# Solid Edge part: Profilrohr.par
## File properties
Username: bmolnar
Dokumentum tartalom típus: 0
Author: bmolnar
Last saved by: bmolnar
Revision: 78
Sűrűség: 0,000 kg/m^3
Pontosság: 0,990
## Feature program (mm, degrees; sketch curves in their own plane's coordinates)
base feature "unnamed BaseFeature 1"
thread "unnamed Thread 1"
thread "Menet_2"  ThreadDepth = 7.5 mm
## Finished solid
Body 1: solid body, 139 faces, 282 edges, 180 vertices, 3 separate solids.
  Faces by surface: plane 82, cylinder 33, cone 20, torus 4
  Edges by curve: line 188, circle 86, curve on surface 7, intersection 1
Bounding box of the edges (mm; curved faces can reach further): 65.000 x 70.000 x 54.500, from (-32.5, -32.5, 0) to (32.5, 37.5, 54.5).
Cylindrical faces by radius (mm): R1.375 x2, R3 x2, R3.4 x4, R4.283 x4, R5.45 x2, R5.5 x8, R25 x1, R25.9 x2, R26.1 x2, R27.6 x2, R43 x4
Conical faces (half-angle, radius in mm at the cone's reference point): 30 deg R3.2887 x2, 30 deg R25.325 x2, 30 deg R26.1887 x2, 45 deg R3.25 x2, 45 deg R3.65 x2, 45 deg R4.533 x2, 45 deg R5.2 x4, 45 deg R26.25 x2, 45 deg R26.35 x2
Toroidal faces (ring radius, tube radius in mm): R27.4 r0.2 x4
Planar faces by outward normal: +x 9, +y 11, +z 10, -x 9, -y 9, -z 10, oblique 24
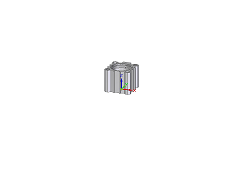
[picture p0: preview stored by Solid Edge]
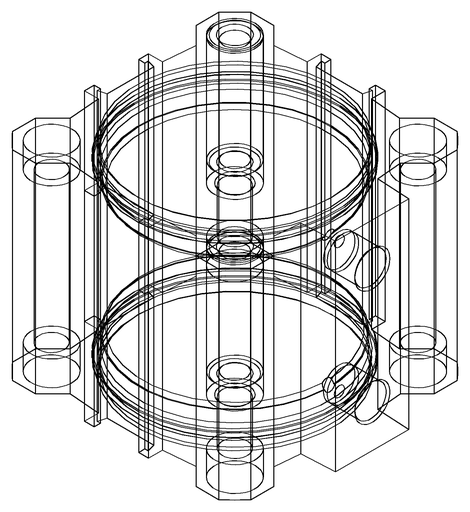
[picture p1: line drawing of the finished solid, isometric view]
